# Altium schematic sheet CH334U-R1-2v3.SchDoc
size 209 x 148 mm; PageSetup: Record=PageOptions¦CenterHorizontal=True¦CenterVertical=True¦PrintScale=0.65¦XCorrection=1.00¦YCorrection=1.00¦PrintKind=1¦BorderSize=5000000¦LeftOffset=0¦BottomOffset=0¦Orientation=2¦PaperLength=1000¦PaperWidth=1000¦Scale=100¦PaperSource=7¦PrintQuality=-4¦MediaType=1¦DitherType=10¦PaperKind=16 开 195x270¦PrintScaleMode=1
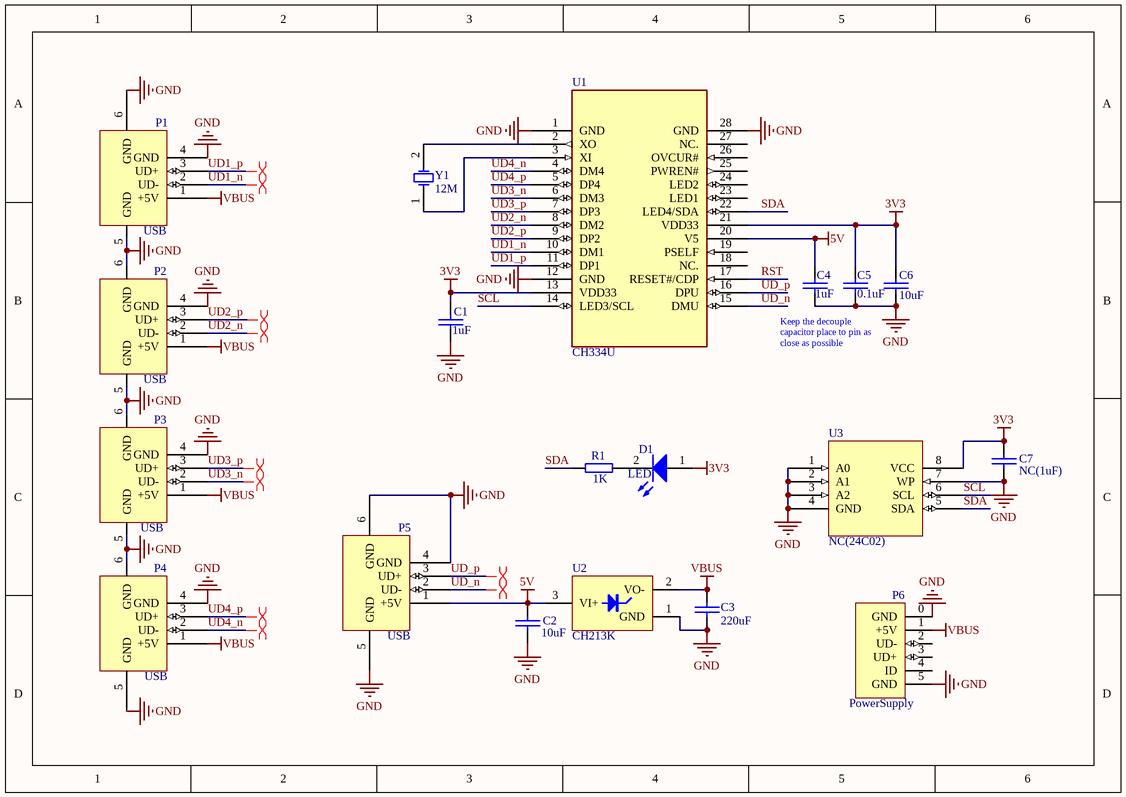
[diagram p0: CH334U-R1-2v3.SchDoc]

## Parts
C1  1uF  [0603_C]
C2  10uF  [0603_C]
C3  220uF  [CD0.1]
C4  1uF  [0603_C]
C5  0.1uF  [0603_C]
C6  10uF  [0603_C]
C7  NC(1uF)  [0603_C]
D1  LED  [0603+]
P1  USB  [USB2.0-A-F-TH_4P-V_13.7mm]
P2  USB  [USB2.0-A-F-TH_4P-V_13.7mm]
P3  USB  [USB2.0-A-F-TH_4P-V_13.7mm]
P4  USB  [USBAF]
P5  USB  [USBAF]
P6  PowerSupply  [USBMICROB-02-GXPX-A1T2]
R1  1K  [0603_R]
U1  CH334U  [QSOP28]
U2  CH213K  [SOT-23-3]
U3  NC(24C02)  [SOIC-8_150mil]
Y1  12M  [XT_AT49]

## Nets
3V3: C1.1 C5.1 C6.1 C7.1 D1.1(A) U1.13(VDD33) U1.21(VDD33) U3.8(VCC)
5V: C2.1 C4.1 P5.1(+5V) U1.20(V5) U2.3(VI+)
GND: C1.2 C2.2 C3.2 C4.2 C5.2 C6.2 C7.2 P1.4(GND) P1.5(GND) P1.6(GND) P2.4(GND) P2.5(GND) P2.6(GND) P3.4(GND) P3.5(GND) P3.6(GND) P4.4(GND) P4.5(GND) P4.6(GND) P5.4(GND) P5.5(GND) P5.6(GND) P6.0(GND) P6.5(GND) U1.1(GND) U1.12(GND) U1.28(GND) U2.1(GND) U3.1(A0) U3.2(A1) U3.3(A2) U3.4(GND) U3.7(WP)
VBUS: C3.1 P1.1(+5V) P2.1(+5V) P3.1(+5V) P4.1(+5V) P6.1(+5V) U2.2(VO-)
RST: U1.17(RESET#/CDP)
SCL: U1.14(LED3/SCL) U3.6(SCL)
SDA: R1.1 U1.22(LED4/SDA) U3.5(SDA)
UD1_n: P1.2(UD-) U1.10(DM1)
UD1_p: P1.3(UD+) U1.11(DP1)
UD2_n: P2.2(UD-) U1.8(DM2)
UD2_p: P2.3(UD+) U1.9(DP2)
UD3_n: P3.2(UD-) U1.6(DM3)
UD3_p: P3.3(UD+) U1.7(DP3)
UD4_n: P4.2(UD-) U1.4(DM4)
UD4_p: P4.3(UD+) U1.5(DP4)
UD_n: P5.2(UD-) U1.15(DMU)
UD_p: P5.3(UD+) U1.16(DPU)
NetD1_2: D1.2(K) R1.2
NetU1_2: U1.2(XO) Y1.2(OSC2)
NetU1_3: U1.3(XI) Y1.1(OSC1)

Not connected (* = marked no-connect by the designer): P6 2(UD-) 3(UD+) 4(ID); U1 18(NC.) 19(PSELF) 23(LED1) 24(LED2) 25(PWREN#) 26(OVCUR#) 27(NC.)

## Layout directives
differential pair: UD1_n, UD1_p, UD2_n, UD2_p, UD3_n, UD3_p, UD4_n, UD4_p, UD_n, UD_p

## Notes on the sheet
- Keep the decouple capacitor place to pin as close as possible

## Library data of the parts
C1-C7 = CAP: Capacitor
D1 = LED: Typical INFRARED GaAs LED
P1-P5 = USB: USB Port
P6 = MicroUSB: MicroUSB Port
R1 = RES
U1 = CH334U: 4 ports High-Speed USB MTT Hub with over current detect & power control
U2 = CH213K: Ideal Diode 5V*1A
U3 = 24C01
Y1 = XTAL: Crystal Oscillator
